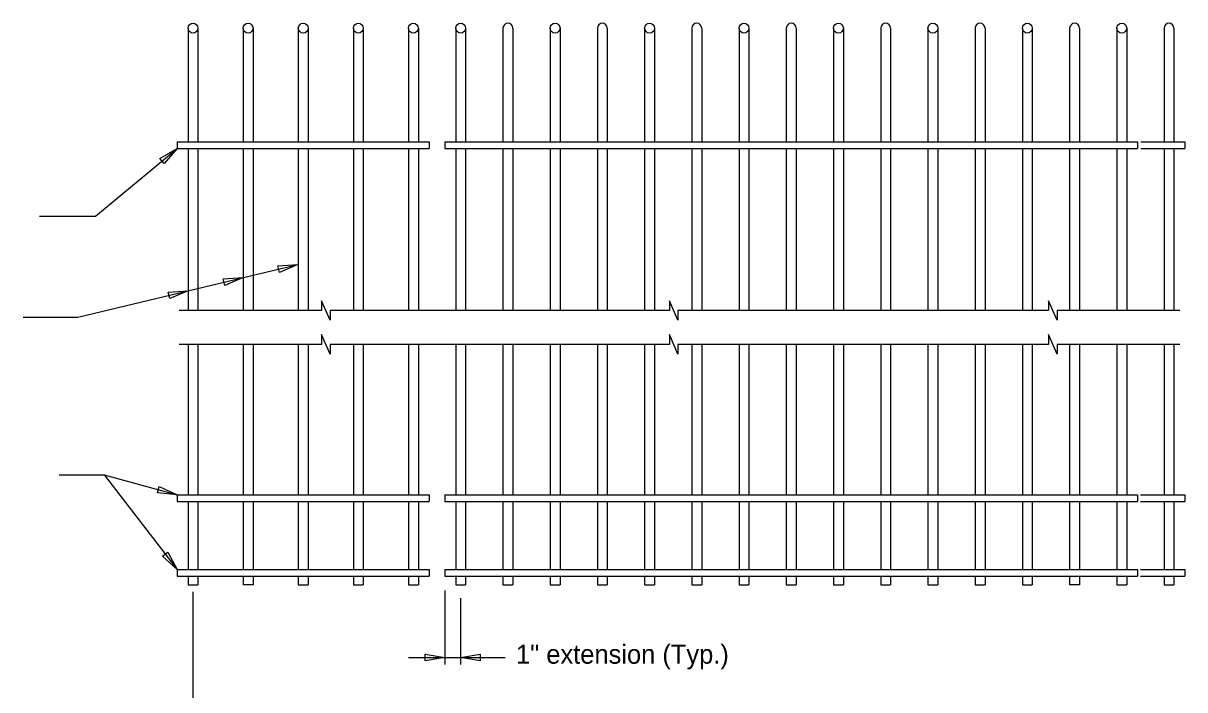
# Model space of a CAD drawing. Extents: x 4.6 to 40.7, y -1.2 to 17.4.
# Drawn here: x 8.14 to 14.29, y 7.29 to 10.82 of the extents above; entities that cross this region are included whole.
import ezdxf

# ---------------------------------------------------------------- set-up
doc = ezdxf.new("R2010")
doc.units = 0
for name, color, linetype in [('AdhocPoint_dp', 7, 'Continuous'), ('PlotBorder_dp', 7, 'Continuous'), ('Rebar_h', 7, 'Continuous'), ('Symbols', 7, 'Continuous')]:
    doc.layers.add(name, color=color, linetype=linetype)

msp = doc.modelspace()

# ---------------------------------------------------------------- linework, layer by layer
at = {"layer": 'AdhocPoint_dp'}
for p, q in [((8.5673, 8.4275), (8.9543, 7.9262)), ((10.371, 7.8157), (10.371, 7.4242)), ((9.0377, 6.3332), (9.0377, 7.8082)), ((10.4543, 7.7749), (10.4543, 7.4242)), ((10.1778, 7.4608), (10.6892, 7.4608))]:
    msp.add_line(p, q, dxfattribs=at)
for points in [[(8.2247, 9.7978), (8.5209, 9.7978), (8.9543, 10.1547)], [(8.1388, 9.2624), (8.4281, 9.2624), (9.5918, 9.541)], [(8.3296, 8.4275), (8.5673, 8.4275), (8.9543, 8.322)]]:
    msp.add_lwpolyline(points, dxfattribs=at)
for points in [[(8.8627, 10.1021), (8.9543, 10.1547), (8.8852, 10.0749)], [(9.4864, 9.5339), (9.5918, 9.541), (9.4946, 9.4996)], [(9.1979, 9.4648), (9.3033, 9.4719), (9.2061, 9.4305)], [(8.9063, 9.395), (9.0116, 9.4021), (8.9145, 9.3607)], [(8.8585, 8.3664), (8.9543, 8.322), (8.8492, 8.3323)], [(8.9047, 8.0194), (8.9543, 7.9262), (8.8767, 7.9978)], [(10.2669, 7.4784), (10.371, 7.4608), (10.2669, 7.4431)], [(10.5585, 7.4431), (10.4543, 7.4608), (10.5585, 7.4784)]]:
    msp.add_lwpolyline(points, close=True, dxfattribs=at)
at = {"layer": 'PlotBorder_dp'}
for p, q in [((9.0116, 10.792), (9.0116, 10.1898)), ((9.0637, 10.792), (9.0637, 10.1898)), ((9.3033, 10.792), (9.3033, 10.1898)), ((9.3554, 10.792), (9.3554, 10.1898)), ((9.595, 10.792), (9.595, 10.1898)), ((9.647, 10.792), (9.647, 10.1898)), ((9.8866, 10.792), (9.8866, 10.1898)), ((9.9387, 10.792), (9.9387, 10.1898)), ((10.1783, 10.792), (10.1783, 10.1898)), ((10.2304, 10.792), (10.2304, 10.1898)), ((10.4283, 10.792), (10.4283, 10.1898)), ((10.4804, 10.792), (10.4804, 10.1898)), ((10.9283, 10.792), (10.9283, 10.1898)), ((10.9804, 10.792), (10.9804, 10.1898)), ((11.4283, 10.792), (11.4283, 10.1898)), ((11.4804, 10.792), (11.4804, 10.1898)), ((11.9283, 10.792), (11.9283, 10.1898)), ((11.9804, 10.792), (11.9804, 10.1898)), ((12.4283, 10.792), (12.4283, 10.1898)), ((12.4804, 10.792), (12.4804, 10.1898)), ((12.9283, 10.792), (12.9283, 10.1898)), ((12.9804, 10.792), (12.9804, 10.1898)), ((13.4283, 10.792), (13.4283, 10.1898)), ((13.4804, 10.792), (13.4804, 10.1898)), ((13.9283, 10.792), (13.9283, 10.1898)), ((13.9804, 10.792), (13.9804, 10.1898)), ((8.9543, 10.1898), (10.2877, 10.1898)), ((8.9543, 10.1898), (8.9543, 10.1547)), ((8.9543, 10.1547), (10.2877, 10.1547)), ((9.0116, 10.1547), (9.0116, 9.2976)), ((9.0637, 10.1547), (9.0637, 9.2976)), ((9.3033, 10.1547), (9.3033, 9.2976)), ((9.3554, 10.1547), (9.3554, 9.2976)), ((9.595, 10.1547), (9.595, 9.2976)), ((9.647, 10.1547), (9.647, 9.2976)), ((9.8866, 10.1547), (9.8866, 9.2976)), ((9.9387, 10.1547), (9.9387, 9.2976)), ((10.1783, 10.1547), (10.1783, 9.2976)), ((10.2304, 10.1547), (10.2304, 9.2976)), ((10.2877, 10.1898), (10.2877, 10.1547)), ((10.371, 10.1898), (10.371, 10.1547)), ((10.371, 10.1898), (14.0377, 10.1898)), ((10.371, 10.1547), (14.0377, 10.1547)), ((10.4283, 10.1547), (10.4283, 9.2976)), ((10.4804, 10.1547), (10.4804, 9.2976)), ((10.9283, 10.1547), (10.9283, 9.2976)), ((10.9804, 10.1547), (10.9804, 9.2976)), ((11.4283, 10.1547), (11.4283, 9.2976)), ((11.4804, 10.1547), (11.4804, 9.2976)), ((11.9283, 10.1547), (11.9283, 9.2976)), ((11.9804, 10.1547), (11.9804, 9.2976)), ((12.4283, 10.1547), (12.4283, 9.2976)), ((12.4804, 10.1547), (12.4804, 9.2976)), ((12.9283, 10.1547), (12.9283, 9.2976)), ((12.9804, 10.1547), (12.9804, 9.2976)), ((13.4283, 10.1547), (13.4283, 9.2976)), ((13.4804, 10.1547), (13.4804, 9.2976)), ((13.9283, 10.1547), (13.9283, 9.2976)), ((13.9804, 10.1547), (13.9804, 9.2976)), ((14.0377, 10.1898), (14.0377, 10.1547)), ((9.0116, 9.1186), (9.0116, 8.322)), ((9.0637, 9.1186), (9.0637, 8.322)), ((9.3033, 9.1186), (9.3033, 8.322)), ((9.3554, 9.1186), (9.3554, 8.322)), ((9.595, 9.1186), (9.595, 8.322)), ((9.647, 9.1186), (9.647, 8.322)), ((9.8866, 9.1186), (9.8866, 8.322)), ((9.9387, 9.1186), (9.9387, 8.322)), ((10.1783, 9.1186), (10.1783, 8.322)), ((10.2304, 9.1186), (10.2304, 8.322)), ((10.4283, 9.1186), (10.4283, 8.322)), ((10.4804, 9.1186), (10.4804, 8.322)), ((10.9283, 9.1186), (10.9283, 8.322)), ((10.9804, 9.1186), (10.9804, 8.322)), ((11.4283, 9.1186), (11.4283, 8.322)), ((11.4804, 9.1186), (11.4804, 8.322)), ((11.9283, 9.1186), (11.9283, 8.322)), ((11.9804, 9.1186), (11.9804, 8.322)), ((12.4283, 9.1186), (12.4283, 8.322)), ((12.4804, 9.1186), (12.4804, 8.322)), ((12.9283, 9.1186), (12.9283, 8.322)), ((12.9804, 9.1186), (12.9804, 8.322)), ((13.4283, 9.1186), (13.4283, 8.322)), ((13.4804, 9.1186), (13.4804, 8.322)), ((13.9283, 9.1186), (13.9283, 8.322)), ((13.9804, 9.1186), (13.9804, 8.322)), ((8.9543, 8.322), (10.2877, 8.322)), ((8.9543, 8.322), (8.9543, 8.2868)), ((10.2877, 8.322), (10.2877, 8.2868)), ((10.371, 8.322), (10.371, 8.2868)), ((10.371, 8.322), (14.0377, 8.322)), ((14.0377, 8.322), (14.0377, 8.2868)), ((8.9543, 8.2868), (10.2877, 8.2868)), ((9.0116, 8.2868), (9.0116, 7.9262)), ((9.0637, 8.2868), (9.0637, 7.9262)), ((9.3033, 8.2868), (9.3033, 7.9262)), ((9.3554, 8.2868), (9.3554, 7.9262)), ((9.595, 8.2868), (9.595, 7.9262)), ((9.647, 8.2868), (9.647, 7.9262)), ((9.8866, 8.2868), (9.8866, 7.9262)), ((9.9387, 8.2868), (9.9387, 7.9262)), ((10.1783, 8.2868), (10.1783, 7.9262)), ((10.2304, 8.2868), (10.2304, 7.9262)), ((10.371, 8.2868), (14.0377, 8.2868)), ((10.4283, 8.2868), (10.4283, 7.9262)), ((10.4804, 8.2868), (10.4804, 7.9262)), ((10.9283, 8.2868), (10.9283, 7.9262)), ((10.9804, 8.2868), (10.9804, 7.9262)), ((11.4283, 8.2868), (11.4283, 7.9262)), ((11.4804, 8.2868), (11.4804, 7.9262)), ((11.9283, 8.2868), (11.9283, 7.9262)), ((11.9804, 8.2868), (11.9804, 7.9262)), ((12.4283, 8.2868), (12.4283, 7.9262)), ((12.4804, 8.2868), (12.4804, 7.9262)), ((12.9283, 8.2868), (12.9283, 7.9262)), ((12.9804, 8.2868), (12.9804, 7.9262)), ((13.4283, 8.2868), (13.4283, 7.9262)), ((13.4804, 8.2868), (13.4804, 7.9262)), ((13.9283, 8.2868), (13.9283, 7.9262)), ((13.9804, 8.2868), (13.9804, 7.9262)), ((8.9543, 7.9262), (10.2877, 7.9262)), ((8.9543, 7.9262), (8.9543, 7.891)), ((8.9543, 7.891), (10.2877, 7.891)), ((9.0116, 7.891), (9.0116, 7.8461)), ((9.0637, 7.891), (9.0637, 7.8461)), ((9.3033, 7.891), (9.3033, 7.8461)), ((9.3554, 7.891), (9.3554, 7.8461)), ((9.595, 7.891), (9.595, 7.8461)), ((9.647, 7.891), (9.647, 7.8461)), ((9.8866, 7.891), (9.8866, 7.8461)), ((9.9387, 7.891), (9.9387, 7.8461)), ((10.1783, 7.891), (10.1783, 7.8461)), ((10.2304, 7.891), (10.2304, 7.8461)), ((10.2877, 7.9262), (10.2877, 7.891)), ((10.371, 7.9262), (10.371, 7.891)), ((10.371, 7.9262), (14.0377, 7.9262)), ((10.371, 7.891), (14.0377, 7.891)), ((10.4283, 7.891), (10.4283, 7.8461)), ((10.4804, 7.891), (10.4804, 7.8461)), ((10.9283, 7.891), (10.9283, 7.8461)), ((10.9804, 7.891), (10.9804, 7.8461)), ((11.4283, 7.891), (11.4283, 7.8461)), ((11.4804, 7.891), (11.4804, 7.8461)), ((11.9283, 7.891), (11.9283, 7.8461)), ((11.9804, 7.891), (11.9804, 7.8461)), ((12.4283, 7.891), (12.4283, 7.8461)), ((12.4804, 7.891), (12.4804, 7.8461)), ((12.9283, 7.891), (12.9283, 7.8461)), ((12.9804, 7.891), (12.9804, 7.8461)), ((13.4283, 7.891), (13.4283, 7.8461)), ((13.4804, 7.891), (13.4804, 7.8461)), ((13.9283, 7.891), (13.9283, 7.8461)), ((13.9804, 7.891), (13.9804, 7.8461)), ((14.0377, 7.9262), (14.0377, 7.891)), ((9.0116, 7.8461), (9.0637, 7.8461)), ((9.3554, 7.8461), (9.3033, 7.8461)), ((9.595, 7.8461), (9.647, 7.8461)), ((9.8866, 7.8461), (9.9387, 7.8461)), ((10.1783, 7.8461), (10.2304, 7.8461)), ((10.4283, 7.8461), (10.4804, 7.8461)), ((10.9283, 7.8461), (10.9804, 7.8461)), ((11.4283, 7.8461), (11.4804, 7.8461)), ((11.9283, 7.8461), (11.9804, 7.8461)), ((12.4283, 7.8461), (12.4804, 7.8461)), ((12.9283, 7.8461), (12.9804, 7.8461)), ((13.4283, 7.8461), (13.4804, 7.8461)), ((13.9283, 7.8461), (13.9804, 7.8461))]:
    msp.add_line(p, q, dxfattribs=at)
for centre in [(9.0377, 10.792), (9.3293, 10.792), (9.621, 10.792), (9.9127, 10.792), (10.2043, 10.792), (10.4543, 10.792), (10.9543, 10.792), (11.4543, 10.792), (11.9543, 10.792), (12.4543, 10.792), (12.9543, 10.792), (13.4543, 10.792), (13.9543, 10.792)]:
    msp.add_circle(centre, 0.026, dxfattribs=at)
at = {"layer": 'Rebar_h'}
for p, q in [((10.6783, 10.792), (10.6783, 10.1898)), ((10.7304, 10.792), (10.7304, 10.1898)), ((11.1783, 10.792), (11.1783, 10.1898)), ((11.2304, 10.792), (11.2304, 10.1898)), ((11.6783, 10.792), (11.6783, 10.1898)), ((11.7304, 10.792), (11.7304, 10.1898)), ((12.1783, 10.792), (12.1783, 10.1898)), ((12.2304, 10.792), (12.2304, 10.1898)), ((12.6783, 10.792), (12.6783, 10.1898)), ((12.7304, 10.792), (12.7304, 10.1898)), ((13.1783, 10.792), (13.1783, 10.1898)), ((13.2304, 10.792), (13.2304, 10.1898)), ((13.6783, 10.792), (13.6783, 10.1898)), ((13.7304, 10.792), (13.7304, 10.1898)), ((14.1783, 10.792), (14.1783, 10.1898)), ((14.2304, 10.792), (14.2304, 10.1898)), ((10.6783, 10.1547), (10.6783, 9.2976)), ((10.7304, 10.1547), (10.7304, 9.2976)), ((11.1783, 10.1547), (11.1783, 9.2976)), ((11.2304, 10.1547), (11.2304, 9.2976)), ((11.6783, 10.1547), (11.6783, 9.2976)), ((11.7304, 10.1547), (11.7304, 9.2976)), ((12.1783, 10.1547), (12.1783, 9.2976)), ((12.2304, 10.1547), (12.2304, 9.2976)), ((12.6783, 10.1547), (12.6783, 9.2976)), ((12.7304, 10.1547), (12.7304, 9.2976)), ((13.1783, 10.1547), (13.1783, 9.2976)), ((13.2304, 10.1547), (13.2304, 9.2976)), ((13.6783, 10.1547), (13.6783, 9.2976)), ((13.7304, 10.1547), (13.7304, 9.2976)), ((14.0542, 10.1898), (14.2877, 10.1898)), ((14.0542, 10.1547), (14.2877, 10.1547)), ((14.1783, 10.1547), (14.1783, 9.2976)), ((14.2304, 10.1547), (14.2304, 9.2976)), ((14.2877, 10.1898), (14.2877, 10.1547)), ((10.6783, 9.1186), (10.6783, 8.322)), ((10.7304, 9.1186), (10.7304, 8.322)), ((11.1783, 9.1186), (11.1783, 8.322)), ((11.2304, 9.1186), (11.2304, 8.322)), ((11.6783, 9.1186), (11.6783, 8.322)), ((11.7304, 9.1186), (11.7304, 8.322)), ((12.1783, 9.1186), (12.1783, 8.322)), ((12.2304, 9.1186), (12.2304, 8.322)), ((12.6783, 9.1186), (12.6783, 8.322)), ((12.7304, 9.1186), (12.7304, 8.322)), ((13.1783, 9.1186), (13.1783, 8.322)), ((13.2304, 9.1186), (13.2304, 8.322)), ((13.6783, 9.1186), (13.6783, 8.322)), ((13.7304, 9.1186), (13.7304, 8.322)), ((14.1783, 9.1186), (14.1783, 8.322)), ((14.2304, 9.1186), (14.2304, 8.322)), ((14.053, 8.322), (14.2877, 8.322)), ((14.2877, 8.322), (14.2877, 8.2868)), ((10.6783, 8.2868), (10.6783, 7.9262)), ((10.7304, 8.2868), (10.7304, 7.9262)), ((11.1783, 8.2868), (11.1783, 7.9262)), ((11.2304, 8.2868), (11.2304, 7.9262)), ((11.6783, 8.2868), (11.6783, 7.9262)), ((11.7304, 8.2868), (11.7304, 7.9262)), ((12.1783, 8.2868), (12.1783, 7.9262)), ((12.2304, 8.2868), (12.2304, 7.9262)), ((12.6783, 8.2868), (12.6783, 7.9262)), ((12.7304, 8.2868), (12.7304, 7.9262)), ((13.1783, 8.2868), (13.1783, 7.9262)), ((13.2304, 8.2868), (13.2304, 7.9262)), ((13.6783, 8.2868), (13.6783, 7.9262)), ((13.7304, 8.2868), (13.7304, 7.9262)), ((14.053, 8.2868), (14.2877, 8.2868)), ((14.1783, 8.2868), (14.1783, 7.9262)), ((14.2304, 8.2868), (14.2304, 7.9262)), ((10.6783, 7.891), (10.6783, 7.8461)), ((10.7304, 7.891), (10.7304, 7.8461)), ((11.1783, 7.891), (11.1783, 7.8461)), ((11.2304, 7.891), (11.2304, 7.8461)), ((11.6783, 7.891), (11.6783, 7.8461)), ((11.7304, 7.891), (11.7304, 7.8461)), ((12.1783, 7.891), (12.1783, 7.8461)), ((12.2304, 7.891), (12.2304, 7.8461)), ((12.6783, 7.891), (12.6783, 7.8461)), ((12.7304, 7.891), (12.7304, 7.8461)), ((13.1783, 7.891), (13.1783, 7.8461)), ((13.2304, 7.891), (13.2304, 7.8461)), ((13.6783, 7.891), (13.6783, 7.8461)), ((13.7304, 7.891), (13.7304, 7.8461)), ((14.053, 7.9262), (14.2877, 7.9262)), ((14.053, 7.891), (14.2877, 7.891)), ((14.1783, 7.891), (14.1783, 7.8461)), ((14.2304, 7.891), (14.2304, 7.8461)), ((14.2877, 7.9262), (14.2877, 7.891)), ((10.6783, 7.8461), (10.7304, 7.8461)), ((11.1783, 7.8461), (11.2304, 7.8461)), ((11.6783, 7.8461), (11.7304, 7.8461)), ((12.1783, 7.8461), (12.2304, 7.8461)), ((12.6783, 7.8461), (12.7304, 7.8461)), ((13.1783, 7.8461), (13.2304, 7.8461)), ((13.7304, 7.8461), (13.6783, 7.8461)), ((14.1783, 7.8461), (14.2304, 7.8461))]:
    msp.add_line(p, q, dxfattribs=at)
for centre, start, end in [((10.7043, 10.792), 0.00089, 180), ((11.2043, 10.792), 0.00089, 180), ((11.7043, 10.792), 0.00089, 180), ((12.2043, 10.792), 0.00089, 180), ((12.7043, 10.792), 0.00089, 180), ((13.2043, 10.792), 0.00089, 180), ((13.7043, 10.792), 0, 179.99911), ((14.2043, 10.792), 0, 180)]:
    msp.add_arc(centre, 0.026, start, end, dxfattribs=at)
at = {"layer": 'Symbols'}
for points in [[(10.2679, 9.2976), (9.7628, 9.2976), (9.7628, 9.246), (9.7178, 9.3493), (9.7178, 9.2976), (8.9649, 9.2976)], [(13.0428, 9.2976), (11.6047, 9.2976), (11.6047, 9.246), (11.5597, 9.3493), (11.5597, 9.2976), (10.2679, 9.2976)], [(14.2613, 9.2976), (13.6117, 9.2976), (13.6117, 9.246), (13.5667, 9.3493), (13.5667, 9.2976), (13.0428, 9.2976)], [(10.2679, 9.1186), (9.7628, 9.1186), (9.7628, 9.0669), (9.7178, 9.1703), (9.7178, 9.1186), (8.9649, 9.1186)], [(13.0494, 9.1186), (11.6047, 9.1186), (11.6047, 9.0669), (11.5597, 9.1703), (11.5597, 9.1186), (10.2679, 9.1186)], [(14.2613, 9.1186), (13.6117, 9.1186), (13.6117, 9.0669), (13.5667, 9.1703), (13.5667, 9.1186), (13.0494, 9.1186)]]:
    msp.add_lwpolyline(points, dxfattribs=at)

# ---------------------------------------------------------------- texts
at = {"layer": 'AdhocPoint_dp'}
msp.add_text('1" extension (Typ.)', height=0.1008, dxfattribs=at).set_placement((10.7475, 7.4283))

doc.saveas('drawing.dxf')
